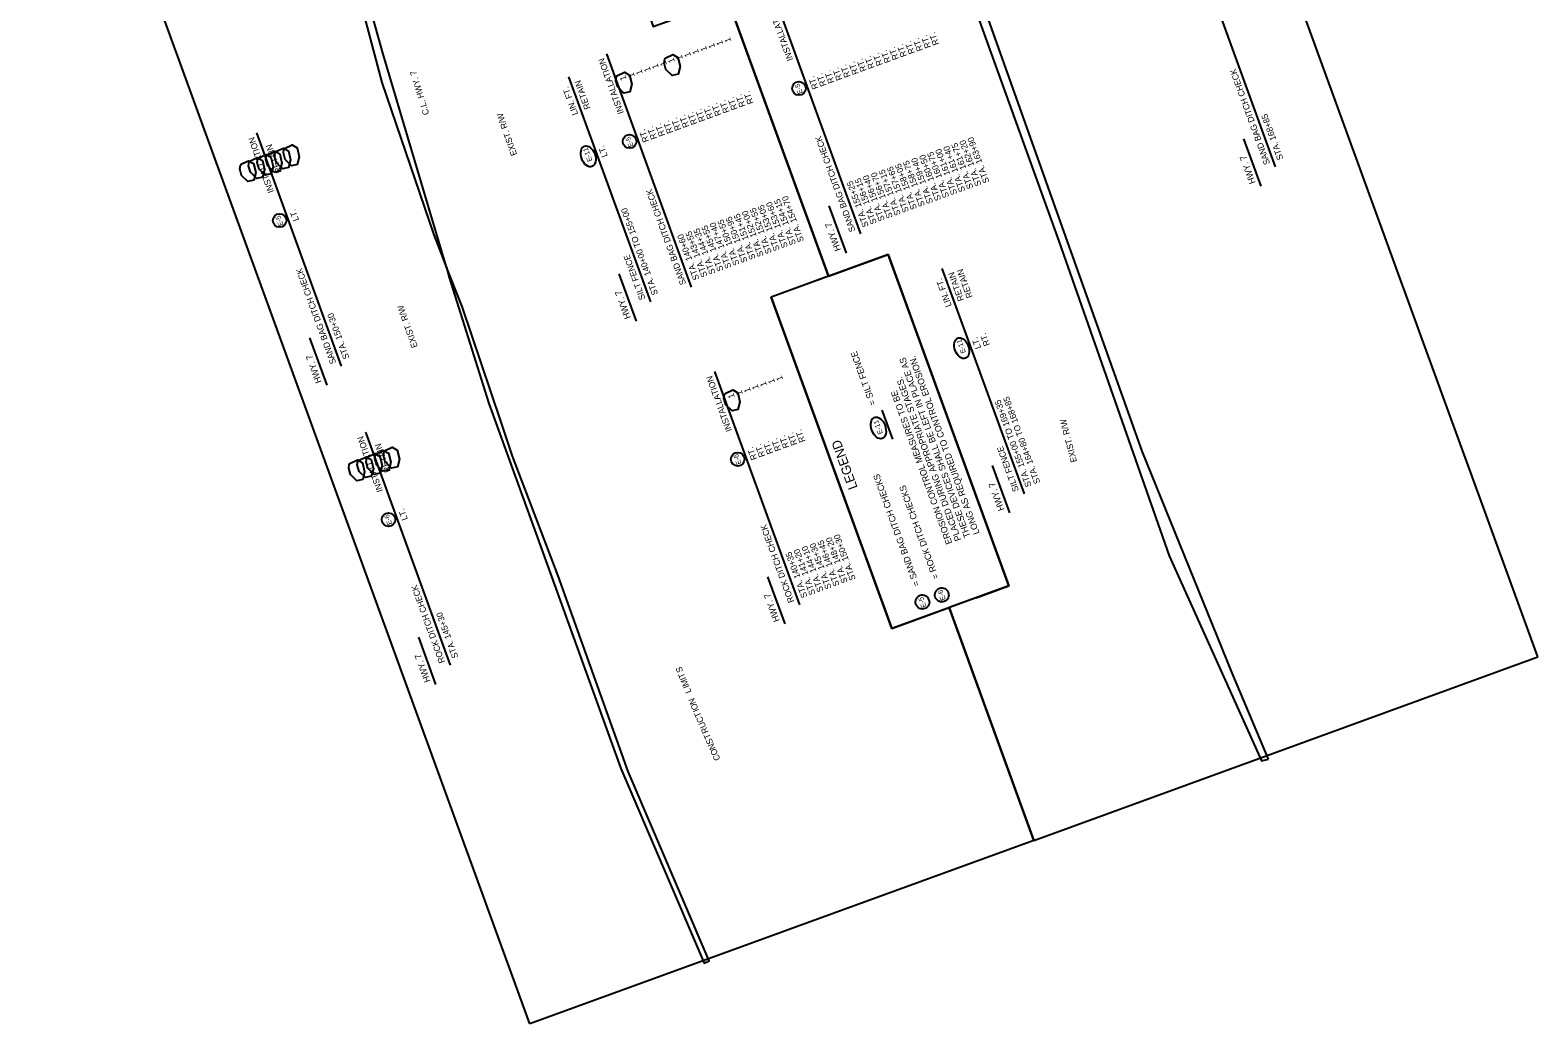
# Model space of a CAD drawing. Extents: x 986289 to 987754, y 1871116 to 1872971.
# Drawn here: x 986289 to 987754, y 1871116 to 1872081 of the extents above; entities that cross this region are included whole.
import ezdxf

# ---------------------------------------------------------------- set-up
doc = ezdxf.new("R2010")
doc.units = 0
for name, color, linetype in [('1', 7, 'Continuous'), ('44', 7, 'Continuous'), ('Level 1', 7, 'Continuous'), ('Level 44', 7, 'Continuous'), ('NO PLOT', 7, 'Continuous'), ('R_Draft', 7, 'Continuous'), ('S_TREE', 7, 'Continuous')]:
    doc.layers.add(name, color=color, linetype=linetype)

msp = doc.modelspace()

# ---------------------------------------------------------------- linework, layer by layer
at = {"layer": '1'}
for p, q in [((987064.5, 1871841.9), (986966.6, 1872110.8)), ((987122.5, 1871863), (987008.8, 1871821.6)), ((987125.9, 1871499.6), (987008.8, 1871821.6)), ((987207.8, 1871529.4), (987125.9, 1871499.6)), ((987263.9, 1871293.8), (987181.7, 1871519.9))]:
    msp.add_line(p, q, dxfattribs=at)
msp.add_lwpolyline([(987207.8, 1871529.4), (987239.7, 1871541), (987122.5, 1871863)], dxfattribs=at)
for centre in [(987035.7, 1872024.3), (986871.1, 1871972.8), (986531.1, 1871896), (986976.2, 1871664.1), (986636.9, 1871605.4)]:
    msp.add_circle(centre, 6.61, dxfattribs=at)
for centre in [(986831, 1871958.3), (987193.9, 1871772)]:
    msp.add_ellipse(centre, major_axis=(-3.6, 9.89), ratio=0.638788, dxfattribs=at)
at = {"layer": '44'}
for p, q in [((987498.8, 1871948.1), (987416.4, 1872174.6)), ((987095.9, 1871882.9), (987013.5, 1872109.3)), ((986931.3, 1871831.3), (986848.9, 1872057.8)), ((986891.7, 1871816.9), (986812.1, 1872035.7)), ((986591.3, 1871754.6), (986508.9, 1871981.1)), ((987484.7, 1871929.5), (987468, 1871975.4)), ((987081.8, 1871864.2), (987065.1, 1871910.1)), ((987254.7, 1871630.6), (987175, 1871849.3)), ((986877.7, 1871798.3), (986860.9, 1871844.2)), ((986577.3, 1871736), (986560.6, 1871781.9)), ((987036.4, 1871522.7), (986954, 1871749.2)), ((986697.1, 1871464), (986614.7, 1871690.4)), ((987240.6, 1871612), (987223.9, 1871657.9)), ((987022.3, 1871504.1), (987005.6, 1871550)), ((986683, 1871445.4), (986666.3, 1871491.2))]:
    msp.add_line(p, q, dxfattribs=at)
at = {"layer": 'Level 1'}
for centre, major_axis, ratio in [((987112.9, 1871694.5), (-3.7, 10.3), 0.622952), ((987174.5, 1871532.3), (2.35, -6.47), 0.97521), ((987155.7, 1871525.4), (2.35, -6.47), 0.97521)]:
    msp.add_ellipse(centre, major_axis=major_axis, ratio=ratio, dxfattribs=at)
at = {"layer": 'Level 44'}
msp.add_lwpolyline([(987126.8, 1871683.5), (987116.5, 1871711.8)], dxfattribs=at)
at = {"layer": 'NO PLOT'}
for points in [[(987753.7, 1871472.1), (987208, 1872971.2), (986718.3, 1872793), (986821.2, 1872510.2), (986884.7, 1872533.2), (987030, 1872133.9), (986966.6, 1872110.8), (987064.5, 1871841.9), (987122.5, 1871863), (987239.7, 1871541), (987181.7, 1871519.9), (987263.9, 1871293.8)], [(987753.7, 1871472.1), (987208, 1872971.2), (986718.3, 1872793), (986821.2, 1872510.2), (986884.7, 1872533.2), (987030, 1872133.9), (986966.6, 1872110.8), (987064.5, 1871841.9), (987122.5, 1871863), (987239.7, 1871541), (987181.7, 1871519.9), (987263.9, 1871293.8)], [(987753.7, 1871472.1), (987208, 1872971.2), (986718.3, 1872793), (986821.2, 1872510.2), (986884.7, 1872533.2), (987030, 1872133.9), (986966.6, 1872110.8), (987064.5, 1871841.9), (987122.5, 1871863), (987239.7, 1871541), (987181.7, 1871519.9), (987263.9, 1871293.8)], [(987753.7, 1871472.1), (987208, 1872971.2), (986718.3, 1872793), (986821.2, 1872510.2), (986884.7, 1872533.2), (987030, 1872133.9), (986966.6, 1872110.8), (987064.5, 1871841.9), (987122.5, 1871863), (987239.7, 1871541), (987181.7, 1871519.9), (987263.9, 1871293.8)], [(987491.8, 1871372.7), (987456.2, 1871457.1), (987369.2, 1871671.9), (987295.1, 1871880), (987205.8, 1872130.8), (987121, 1872363), (986947.4, 1872834.5), (986933.7, 1872873.1), (986927.1, 1872871.4), (986945.7, 1872820.2), (986924.6, 1872802.1), (986920.3, 1872785.6), (986930.5, 1872752.2), (986941.1, 1872766.8), (986957.6, 1872786.8), (987010.9, 1872635.9), (987123.9, 1872331.6), (987288.2, 1871875.9), (987395.4, 1871570.4), (987485.3, 1871371)], [(986774.2, 1871115.6), (986369.2, 1872228.3), (986415.6, 1872245.1), (986348.7, 1872429.1), (986362.4, 1872434.1), (986288.7, 1872636.6), (986718.3, 1872793), (986821.2, 1872510.2), (986748.9, 1872483.8), (986894.2, 1872084.4), (986966.6, 1872110.8), (987064.5, 1871841.9), (987008.8, 1871821.6), (987125.9, 1871499.6), (987181.7, 1871519.9), (987263.9, 1871293.8)], [(986774.2, 1871115.6), (986369.2, 1872228.3), (986415.6, 1872245.1), (986348.7, 1872429.1), (986362.4, 1872434.1), (986288.7, 1872636.6), (986718.3, 1872793), (986821.2, 1872510.2), (986748.9, 1872483.8), (986894.2, 1872084.4), (986966.6, 1872110.8), (987064.5, 1871841.9), (987008.8, 1871821.6), (987125.9, 1871499.6), (987181.7, 1871519.9), (987263.9, 1871293.8)], [(986774.2, 1871115.6), (986369.2, 1872228.3), (986415.6, 1872245.1), (986348.7, 1872429.1), (986362.4, 1872434.1), (986288.7, 1872636.6), (986718.3, 1872793), (986821.2, 1872510.2), (986748.9, 1872483.8), (986894.2, 1872084.4), (986966.6, 1872110.8), (987064.5, 1871841.9), (987008.8, 1871821.6), (987125.9, 1871499.6), (987181.7, 1871519.9), (987263.9, 1871293.8)], [(986774.2, 1871115.6), (986369.2, 1872228.3), (986415.6, 1872245.1), (986348.7, 1872429.1), (986362.4, 1872434.1), (986288.7, 1872636.6), (986718.3, 1872793), (986821.2, 1872510.2), (986748.9, 1872483.8), (986894.2, 1872084.4), (986966.6, 1872110.8), (987064.5, 1871841.9), (987008.8, 1871821.6), (987125.9, 1871499.6), (987181.7, 1871519.9), (987263.9, 1871293.8)]]:
    msp.add_lwpolyline(points, close=True, dxfattribs=at)
msp.add_lwpolyline([(986566.3, 1872272.3), (986630.5, 1872029.9), (986681, 1871882), (986692, 1871853.6), (986693, 1871850.9), (986693, 1871850.9), (986693.2, 1871850.3), (986695.9, 1871840.7), (986734.3, 1871718.1), (986785.4, 1871577.2), (986862.7, 1871363.5), (986943.5, 1871174.5), (986948.5, 1871176.8), (986869.9, 1871360.7), (986801.7, 1871550.9), (986757.5, 1871667.2), (986746.1, 1871701.2), (986708.4, 1871812.4), (986693.1, 1871850.8), (986693, 1871851), (986692.8, 1871851.7), (986631.8, 1872057.7), (986585.5, 1872222.9)], dxfattribs=at)
at = {"layer": 'S_TREE'}
for points in [[(986905.8, 1872053.6), (986913.3, 1872057.1), (986918.1, 1872054.4), (986920.3, 1872045.5), (986918.3, 1872038.2), (986912.6, 1872036.9), (986906.5, 1872042.8), (986904.7, 1872049.2), (986905.3, 1872052.9), (986906.5, 1872054.1)], [(986858.9, 1872036.5), (986866.3, 1872040), (986871.2, 1872037.3), (986873.3, 1872028.5), (986871.4, 1872021.1), (986865.7, 1872019.8), (986859.6, 1872025.7), (986857.8, 1872032.1), (986858.4, 1872035.8), (986859.6, 1872037)], [(986518.9, 1871959.8), (986526.3, 1871963.3), (986531.2, 1871960.6), (986533.3, 1871951.7), (986531.4, 1871944.3), (986525.7, 1871943.1), (986519.6, 1871949), (986517.7, 1871955.4), (986518.4, 1871959.1), (986519.5, 1871960.3)], [(986527.3, 1871962.9), (986534.8, 1871966.4), (986539.6, 1871963.6), (986541.8, 1871954.8), (986539.8, 1871947.4), (986534.1, 1871946.1), (986528.1, 1871952), (986526.2, 1871958.5), (986526.8, 1871962.1), (986528, 1871963.4)], [(986527.3, 1871962.9), (986534.8, 1871966.4), (986539.6, 1871963.6), (986541.8, 1871954.8), (986539.8, 1871947.4), (986534.1, 1871946.1), (986528.1, 1871952), (986526.2, 1871958.5), (986526.8, 1871962.1), (986528, 1871963.4)], [(986535.8, 1871966), (986543.3, 1871969.4), (986548.1, 1871966.7), (986550.2, 1871957.9), (986548.3, 1871950.5), (986542.6, 1871949.2), (986536.5, 1871955.1), (986534.7, 1871961.6), (986535.3, 1871965.2), (986536.5, 1871966.4)], [(986493.5, 1871950.6), (986501, 1871954.1), (986505.8, 1871951.3), (986507.9, 1871942.5), (986506, 1871935.1), (986500.3, 1871933.8), (986494.2, 1871939.7), (986492.4, 1871946.2), (986493, 1871949.8), (986494.2, 1871951)], [(986502, 1871953.6), (986509.4, 1871957.1), (986514.3, 1871954.4), (986516.4, 1871945.6), (986514.5, 1871938.2), (986508.8, 1871936.9), (986502.7, 1871942.8), (986500.8, 1871949.2), (986501.4, 1871952.9), (986502.6, 1871954.1)], [(986510.4, 1871956.7), (986517.9, 1871960.2), (986522.7, 1871957.5), (986524.9, 1871948.6), (986522.9, 1871941.3), (986517.2, 1871940), (986511.1, 1871945.9), (986509.3, 1871952.3), (986509.9, 1871956), (986511.1, 1871957.2)], [(986963.9, 1871727.9), (986971.4, 1871731.4), (986976.2, 1871728.6), (986978.4, 1871719.8), (986976.4, 1871712.4), (986970.7, 1871711.1), (986964.7, 1871717), (986962.8, 1871723.5), (986963.4, 1871727.1), (986964.6, 1871728.4)], [(986616.2, 1871666.1), (986623.7, 1871669.6), (986628.5, 1871666.8), (986630.6, 1871658), (986628.7, 1871650.6), (986623, 1871649.4), (986616.9, 1871655.3), (986615.1, 1871661.7), (986615.7, 1871665.4), (986616.9, 1871666.6)], [(986616.2, 1871666.1), (986623.7, 1871669.6), (986628.5, 1871666.8), (986630.6, 1871658), (986628.7, 1871650.6), (986623, 1871649.4), (986616.9, 1871655.3), (986615.1, 1871661.7), (986615.7, 1871665.4), (986616.9, 1871666.6)], [(986624.6, 1871669.2), (986632.1, 1871672.7), (986636.9, 1871669.9), (986639.1, 1871661.1), (986637.2, 1871653.7), (986631.5, 1871652.4), (986625.4, 1871658.3), (986623.5, 1871664.8), (986624.1, 1871668.4), (986625.3, 1871669.6)], [(986633.1, 1871672.3), (986640.6, 1871675.7), (986645.4, 1871673), (986647.6, 1871664.2), (986645.6, 1871656.8), (986639.9, 1871655.5), (986633.8, 1871661.4), (986632, 1871667.9), (986632.6, 1871671.5), (986633.8, 1871672.7)], [(986599.3, 1871659.9), (986606.7, 1871663.4), (986611.6, 1871660.7), (986613.7, 1871651.9), (986611.8, 1871644.5), (986606.1, 1871643.2), (986600, 1871649.1), (986598.2, 1871655.5), (986598.8, 1871659.2), (986600, 1871660.4)], [(986599.3, 1871659.9), (986606.7, 1871663.4), (986611.6, 1871660.7), (986613.7, 1871651.9), (986611.8, 1871644.5), (986606.1, 1871643.2), (986600, 1871649.1), (986598.2, 1871655.5), (986598.8, 1871659.2), (986600, 1871660.4)], [(986607.7, 1871663), (986615.2, 1871666.5), (986620, 1871663.8), (986622.2, 1871654.9), (986620.2, 1871647.6), (986614.5, 1871646.3), (986608.5, 1871652.2), (986606.6, 1871658.6), (986607.2, 1871662.3), (986608.4, 1871663.5)], [(986607.7, 1871663), (986615.2, 1871666.5), (986620, 1871663.8), (986622.2, 1871654.9), (986620.2, 1871647.6), (986614.5, 1871646.3), (986608.5, 1871652.2), (986606.6, 1871658.6), (986607.2, 1871662.3), (986608.4, 1871663.5)]]:
    msp.add_lwpolyline(points, dxfattribs=at)

# ---------------------------------------------------------------- texts
at = {"layer": '1'}
for s, p in [('E-5 ', (987039.5, 1872019.8)), ('E-5 ', (986875, 1871968.3)), ('E-11', (986835, 1871954.2)), ('E-5 ', (986534.9, 1871891.6)), ('E-11', (987197.9, 1871767.9)), ('E-6 ', (986979.9, 1871659.9)), ('E-6 ', (986640.6, 1871601.2))]:
    msp.add_text(s, height=4.8, rotation=110, dxfattribs=at).set_placement(p)
at = {"layer": '44'}
for s, height, p in [('INSTALLATION', 6, (987030.2, 1872052.3)), ('1', 6, (986946.7, 1872061.7)), ('1', 6, (986954.5, 1872064.5)), ('1', 6, (986962.3, 1872067.4)), ('1', 6, (986970.1, 1872070.2)), ('RT.', 6, (987132.9, 1872053.2)), ('RT.', 6, (987140.7, 1872056)), ('RT.', 6, (987148.5, 1872058.9)), ('RT.', 6, (987156.4, 1872061.7)), ('RT.', 6, (987164.2, 1872064.6)), ('RT.', 6, (987172, 1872067.4)), ('INSTALLATION', 6, (986865.7, 1872000.7)), ('1', 6, (986907.6, 1872047.4)), ('1', 6, (986915.3, 1872050.3)), ('1', 6, (986923.2, 1872053.1)), ('1', 6, (986931, 1872056)), ('1', 6, (986938.8, 1872058.8)), ('RT.', 6, (987093.8, 1872038.9)), ('RT.', 6, (987101.6, 1872041.8)), ('RT.', 6, (987109.4, 1872044.6)), ('RT.', 6, (987117.3, 1872047.5)), ('RT.', 6, (987125.1, 1872050.3)), ('1', 6, (986868.4, 1872033.2)), ('1', 6, (986876.3, 1872036)), ('1', 6, (986884.1, 1872038.9)), ('1', 6, (986891.9, 1872041.7)), ('1', 6, (986899.7, 1872044.6)), ('RT.', 6, (987054.7, 1872024.7)), ('RT.', 6, (987062.5, 1872027.5)), ('RT.', 6, (987070.3, 1872030.4)), ('RT.', 6, (987078.1, 1872033.2)), ('RT.', 6, (987085.9, 1872036.1)), ('SAND BAG DITCH CHECK', 6, (987493.6, 1871951.4)), ('LIN. FT.', 6, (986821.3, 1871999.5)), ('RETAIN', 6, (986833.2, 1872005.2)), ('RT.', 6, (986991.8, 1872010.2)), ('RT.', 6, (986952.7, 1871995.9)), ('RT.', 6, (986960.5, 1871998.8)), ('RT.', 6, (986968.3, 1872001.6)), ('RT.', 6, (986976.2, 1872004.5)), ('RT.', 6, (986984, 1872007.3)), ('RT.', 6, (986913.6, 1871981.7)), ('RT.', 6, (986921.4, 1871984.5)), ('RT.', 6, (986929.2, 1871987.4)), ('RT.', 6, (986937.1, 1871990.2)), ('RT.', 6, (986944.9, 1871993.1)), ('STA. 168+85', 6, (987506.5, 1871956)), ('INSTALLATION', 6, (986525.7, 1871924)), ('RT.', 6, (986890.1, 1871973.2)), ('RT.', 6, (986898, 1871976)), ('RT.', 6, (986905.8, 1871978.9)), ('SAND BAG DITCH CHECK', 6, (987090.7, 1871886.1)), ('STA. 163+90', 6, (987220.9, 1871933.5)), ('RETAIN', 6, (986533.3, 1871943.1)), ('LT.', 6, (986850, 1871958.7)), ('STA. 160+75', 6, (987181.8, 1871919.2)), ('STA. 161+00', 6, (987189.6, 1871922.1)), ('STA. 161+40', 6, (987197.4, 1871924.9)), ('STA. 161+75', 6, (987205.3, 1871927.8)), ('STA. 162+20', 6, (987213.1, 1871930.6)), ('STA. 157+65', 6, (987142.7, 1871905)), ('STA. 158+05', 6, (987150.5, 1871907.8)), ('STA. 158+75', 6, (987158.3, 1871910.7)), ('STA. 159+40', 6, (987166.2, 1871913.5)), ('STA. 160+50', 6, (987174, 1871916.4)), ('HWY. 7', 6.25, (987479.5, 1871932.8)), ('STA. 155+25', 6, (987103.6, 1871890.8)), ('STA. 156+15', 6, (987111.4, 1871893.6)), ('STA. 156+40', 6, (987119.2, 1871896.5)), ('STA. 156+70', 6, (987127, 1871899.3)), ('STA. 157+15', 6, (987134.8, 1871902.1)), ('SAND BAG DITCH CHECK', 6, (986926.2, 1871834.6)), ('STA. 154+70', 6, (987040.7, 1871876.3)), ('LT.', 6, (986550.1, 1871896.6)), ('STA. 140+00 TO 155+00', 6, (986898.9, 1871824.6)), ('STA. 152+00', 6, (987001.6, 1871862)), ('STA. 152+55', 6, (987009.4, 1871864.9)), ('STA. 153+05', 6, (987017.2, 1871867.7)), ('STA. 153+60', 6, (987025.1, 1871870.6)), ('STA. 154+15', 6, (987032.9, 1871873.4)), ('STA. 145+55', 6, (986962.5, 1871847.8)), ('STA. 147+40', 6, (986970.3, 1871850.6)), ('STA. 150+55', 6, (986978.1, 1871853.5)), ('STA. 150+95', 6, (986986, 1871856.3)), ('STA. 151+45', 6, (986993.8, 1871859.2)), ('HWY. 7', 6.25, (987076.6, 1871867.5)), ('STA. 140+60', 6, (986939, 1871839.2)), ('STA. 143+55', 6, (986946.9, 1871842.1)), ('STA. 144+35', 6, (986954.7, 1871844.9)), ('SILT FENCE      ', 6, (986886.6, 1871820.1)), ('SAND BAG DITCH CHECK', 6, (986586.2, 1871757.8)), ('RETAIN', 6, (987196.2, 1871818.9)), ('RETAIN', 6, (987204.6, 1871821.9)), ('LIN. FT.', 6, (987184.2, 1871813.2)), ('HWY. 7', 6.25, (986872.4, 1871801.6)), ('STA. 150+30', 6, (986599, 1871762.5)), ('RT.', 6, (987221.4, 1871775.3)), ('LT.', 6, (987212.9, 1871772.4)), ('HWY. 7', 6.25, (986572.1, 1871739.2)), ('INSTALLATION', 6, (986970.7, 1871692.1)), ('1', 6, (987012.6, 1871738.8)), ('1', 6, (987020.4, 1871741.6)), ('1', 6, (986973.5, 1871724.5)), ('1', 6, (986981.3, 1871727.4)), ('1', 6, (986989.1, 1871730.2)), ('1', 6, (986996.9, 1871733.1)), ('1', 6, (987004.7, 1871735.9)), ('STA. 155+00 TO 169+35', 6, (987261.9, 1871638.3)), ('STA. 164+80 TO 168+85', 6, (987270.3, 1871641.4)), ('INSTALLATION', 6, (986631.5, 1871633.4)), ('RT.', 6, (987018.6, 1871673)), ('RT.', 6, (987026.4, 1871675.9)), ('RT.', 6, (987034.3, 1871678.7)), ('RT.', 6, (987042.1, 1871681.6)), ('RETAIN', 6, (986639.1, 1871652.4)), ('RT.', 6, (986995.2, 1871664.5)), ('RT.', 6, (987003, 1871667.3)), ('RT.', 6, (987010.8, 1871670.2)), ('SILT FENCE      ', 6, (987249.5, 1871633.8)), ('HWY. 7', 6.25, (987235.4, 1871615.2)), ('LT.', 6, (986655.8, 1871605.9)), ('ROCK DITCH CHECK', 6, (987031.2, 1871525.9)), ('STA. 145+30', 6, (987067.5, 1871539.1)), ('STA. 146+45', 6, (987075.3, 1871541.9)), ('STA. 148+20', 6, (987083.2, 1871544.8)), ('STA. 150+30', 6, (987091, 1871547.6)), ('STA. 140+35', 6, (987044.1, 1871530.6)), ('STA. 141+20', 6, (987051.9, 1871533.4)), ('STA. 144+10', 6, (987059.7, 1871536.3)), ('ROCK DITCH CHECK', 6, (986691.9, 1871467.2)), ('HWY. 7', 6.25, (987017.1, 1871507.3)), ('STA. 145+30', 6, (986704.8, 1871471.9)), ('HWY. 7', 6.25, (986677.8, 1871448.6))]:
    msp.add_text(s, height=height, rotation=110, dxfattribs=at).set_placement(p)
at = {"layer": 'Level 1'}
for s, height, p in [('= SILT FENCE', 6.25, (987110.6, 1871717.6)), ('THESE DEVICES SHALL BE LEFT IN PLACE AS ', 6.25, (987202.4, 1871589.1)), ('LONG AS REQUIRED TO CONTROL EROSION.', 6.25, (987211.3, 1871592.3)), ('PLACED DURING APPROPRIATE STAGES. ', 6.25, (987193.6, 1871585.9)), ('EROSION CONTROL MEASURES TO BE', 6.25, (987184.8, 1871582.7)), ('E-11 ', 4.88, (987117.3, 1871689.3)), ('= SAND BAG DITCH CHECKS', 6.25, (987153, 1871542)), ('= ROCK DITCH CHECKS', 6.25, (987171.8, 1871548.9)), ('E-5 ', 4.88, (987159.7, 1871520.9)), ('E-6 ', 4.88, (987178.4, 1871527.9))]:
    msp.add_text(s, height=height, rotation=110, dxfattribs=at).set_placement(p)
at = {"layer": 'Level 44'}
msp.add_text('LEGEND', height=9.14, rotation=110, dxfattribs=at).set_placement((987092.8, 1871636.6))
at = {"layer": 'R_Draft'}
for s, rotation, p in [('C.L. HWY. 7', 107.2156, (986676.5, 1871999.5)), ('EXIST. R/W', 109.2927, (986761.9, 1871960.1)), ('EXIST. R/W', 109.2927, (986665.3, 1871773.5)), ('EXIST. R/W', 104.7013, (987305.9, 1871661.9)), ('S', 111.9918, (986923.3, 1871458.2)), ('T', 112.0093, (986925.5, 1871452.7)), ('I', 112.0093, (986926.3, 1871450.9)), ('M', 111.7971, (986928.7, 1871444.9)), ('I', 111.7971, (986929.4, 1871443.1)), ('L', 112.0692, (986931.4, 1871438.1)), ('N', 112.6761, (986935.8, 1871427.3)), ('O', 112.6761, (986938.1, 1871421.9)), ('I', 112.6761, (986938.8, 1871420.1)), ('T', 113.369, (986941.2, 1871414.8)), ('C', 113.6287, (986943.4, 1871409.6)), ('U', 113.6287, (986945.7, 1871404.4)), ('R', 113.4396, (986948, 1871399.1)), ('T', 113.4726, (986950.3, 1871393.8)), ('S', 113.6258, (986952.6, 1871388.6)), ('N', 114.4462, (986954.9, 1871383.5)), ('O', 113.5183, (986957.2, 1871378)), ('C', 113.5788, (986959.5, 1871372.8))]:
    msp.add_text(s, height=6, rotation=rotation, dxfattribs=at).set_placement(p)

doc.saveas('drawing.dxf')
